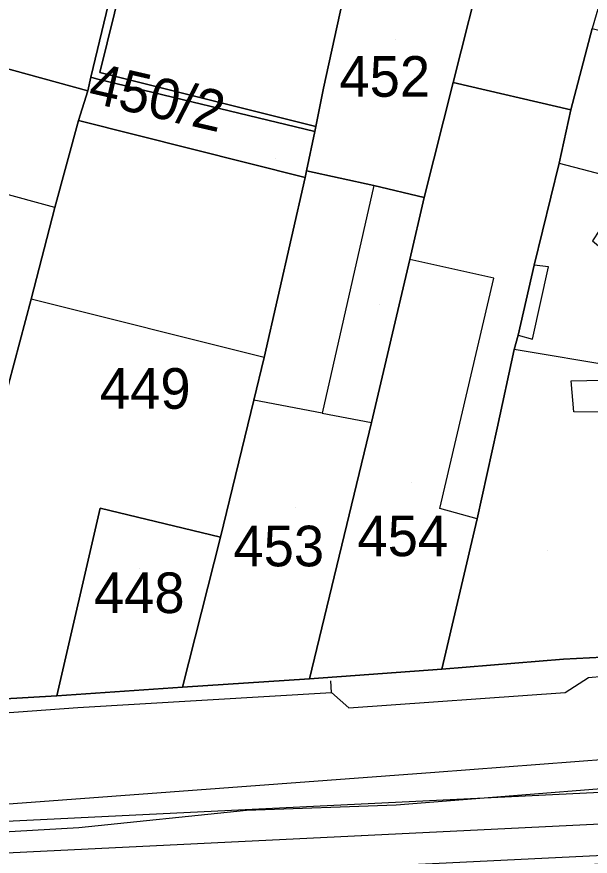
# Model space of a CAD drawing. Extents: x -263423 to -261326, y -1240067 to -1237864.
# Drawn here: x -262993.57 to -262965.35, y -1239820.47 to -1239779.18 of the extents above; entities that cross this region are included whole.
import ezdxf

# ---------------------------------------------------------------- set-up
doc = ezdxf.new("R2010")
doc.units = 0
for name, color, linetype in [('body_kn', 7, 'Continuous'), ('kladpar_druhypozemkov', 7, 'Continuous'), ('kladpar_hranice', 7, 'Continuous'), ('kladpar_parcelnecisla', 7, 'Continuous'), ('kladpar_plochy', 7, 'Continuous'), ('tarchy_linie', 7, 'Continuous'), ('zappar_hrandruhpozemk', 7, 'Continuous')]:
    doc.layers.add(name, color=color, linetype=linetype)

msp = doc.modelspace()

# ---------------------------------------------------------------- linework, layer by layer
at = {"layer": 'body_kn'}
for p, q in [((-262989.49, -1239781.92), (-262989.49, -1239781.92)), ((-262989.92, -1239782.15), (-262989.92, -1239782.15)), ((-262989.92, -1239782.15), (-262989.92, -1239782.15)), ((-262989.64, -1239782.22), (-262989.64, -1239782.22)), ((-262972.09, -1239782.4), (-262972.09, -1239782.4)), ((-262990.08, -1239782.82), (-262990.08, -1239782.82)), ((-262990.08, -1239782.82), (-262990.08, -1239782.82)), ((-262978.47, -1239782.68), (-262978.47, -1239782.68)), ((-262966.3, -1239783.76), (-262966.3, -1239783.76)), ((-262990.53, -1239784.28), (-262990.53, -1239784.28)), ((-262978.91, -1239784.81), (-262978.91, -1239784.81)), ((-262978.86, -1239784.57), (-262978.86, -1239784.57)), ((-262978.86, -1239784.57), (-262978.86, -1239784.57)), ((-262966.88, -1239786.37), (-262966.88, -1239786.37)), ((-262966.88, -1239786.37), (-262966.88, -1239786.37)), ((-262979.32, -1239786.76), (-262979.32, -1239786.76)), ((-262979.38, -1239787.08), (-262979.38, -1239787.08)), ((-262979.38, -1239787.08), (-262979.38, -1239787.08)), ((-262976, -1239787.48), (-262976, -1239787.48)), ((-262976, -1239787.48), (-262976, -1239787.48)), ((-262973.52, -1239788.06), (-262973.52, -1239788.06)), ((-262991.7, -1239788.55), (-262991.7, -1239788.55)), ((-262991.7, -1239788.55), (-262991.7, -1239788.55)), ((-262974.23, -1239791.12), (-262974.23, -1239791.12)), ((-262974.23, -1239791.12), (-262974.23, -1239791.12)), ((-262968.11, -1239791.4), (-262968.11, -1239791.4)), ((-262967.41, -1239791.47), (-262967.41, -1239791.47)), ((-262970.09, -1239792.03), (-262970.09, -1239792.03)), ((-262992.86, -1239793.06), (-262992.86, -1239793.06)), ((-262968.89, -1239794.84), (-262968.89, -1239794.84)), ((-262968.89, -1239794.84), (-262968.89, -1239794.84)), ((-262968.19, -1239795.03), (-262968.19, -1239795.03)), ((-262969.09, -1239795.54), (-262969.09, -1239795.54)), ((-262981.4, -1239795.93), (-262981.4, -1239795.93)), ((-262981.4, -1239795.93), (-262981.4, -1239795.93)), ((-262966.29, -1239797.08), (-262966.29, -1239797.08)), ((-262981.91, -1239798.03), (-262981.91, -1239798.03)), ((-262978.54, -1239798.68), (-262978.54, -1239798.68)), ((-262966.16, -1239798.61), (-262966.16, -1239798.61)), ((-262976.12, -1239799.14), (-262976.12, -1239799.14)), ((-262969.93, -1239799.42), (-262969.93, -1239799.42)), ((-262989.46, -1239803.34), (-262989.46, -1239803.34)), ((-262972.75, -1239803.36), (-262972.75, -1239803.36)), ((-262970.91, -1239803.88), (-262970.91, -1239803.88)), ((-262970.91, -1239803.88), (-262970.91, -1239803.88)), ((-262983.54, -1239804.77), (-262983.54, -1239804.77)), ((-262983.54, -1239804.77), (-262983.54, -1239804.77)), ((-262966.66, -1239810.78), (-262966.66, -1239810.78)), ((-262972.66, -1239811.27), (-262972.66, -1239811.27)), ((-262979.16, -1239811.74), (-262979.16, -1239811.74)), ((-262965.44, -1239811.68), (-262965.44, -1239811.68)), ((-262985.42, -1239812.16), (-262985.42, -1239812.16)), ((-262978.11, -1239811.85), (-262978.11, -1239811.85)), ((-262991.6, -1239812.58), (-262991.6, -1239812.58)), ((-262978.09, -1239812.41), (-262978.09, -1239812.41)), ((-262978.09, -1239812.41), (-262978.09, -1239812.41)), ((-262966.58, -1239812.41), (-262966.58, -1239812.41)), ((-262990.57, -1239813.15), (-262990.57, -1239813.15)), ((-262977.23, -1239813.17), (-262977.23, -1239813.17)), ((-262973, -1239816.36), (-262973, -1239816.36)), ((-262974.9, -1239817.94), (-262974.9, -1239817.94)), ((-262982.27, -1239818.21), (-262982.27, -1239818.21)), ((-262990.52, -1239819.05), (-262990.52, -1239819.05))]:
    msp.add_line(p, q, dxfattribs=at)
at = {"layer": 'kladpar_druhypozemkov'}
for p, q in [((-262974.95, -1239780.31), (-262974.95, -1239780.31)), ((-262980.85, -1239786.14), (-262980.85, -1239786.14)), ((-262975.73, -1239793.32), (-262975.73, -1239793.32)), ((-262987.4, -1239797.24), (-262987.4, -1239797.24)), ((-262974.15, -1239802.11), (-262974.15, -1239802.11)), ((-262979.85, -1239803.31), (-262979.85, -1239803.31)), ((-262967.43, -1239805.42), (-262967.43, -1239805.42)), ((-262987.55, -1239806.31), (-262987.55, -1239806.31))]:
    msp.add_line(p, q, dxfattribs=at)
at = {"layer": 'kladpar_hranice'}
for points in [[(-262966.65, -1239760.75), (-262965.09, -1239754.26), (-262959.11, -1239755.69), (-262960.79, -1239761.74), (-262963.71, -1239774.47), (-262965.26, -1239779.75), (-262966.3, -1239783.76), (-262972.09, -1239782.4), (-262970.54, -1239776.22), (-262967.95, -1239765.91), (-262966.65, -1239760.75)], [(-262986.64, -1239768.57), (-262986.9, -1239769.58), (-262986.92, -1239769.66), (-262989.92, -1239782.15), (-262990.08, -1239782.82), (-262996.71, -1239781), (-262993.93, -1239773.56), (-262993.8, -1239772.86), (-262992.64, -1239768.02), (-262991.98, -1239763.5), (-262991.81, -1239763.66), (-262991.95, -1239764.75), (-262991.23, -1239765.39), (-262990.63, -1239764.79), (-262986.64, -1239768.57)], [(-262978.86, -1239784.57), (-262978.91, -1239784.81), (-262989.64, -1239782.22), (-262989.92, -1239782.15), (-262986.92, -1239769.66), (-262982.94, -1239770.71), (-262981.57, -1239765.49), (-262980.39, -1239765.77), (-262980.6, -1239766.46), (-262980.9, -1239767.72), (-262978.84, -1239768.28), (-262981.01, -1239776.61), (-262983.49, -1239776.01), (-262983.23, -1239774.99), (-262987.48, -1239773.91), (-262988.04, -1239776.06), (-262989.49, -1239781.92), (-262978.86, -1239784.57)], [(-262976.72, -1239774.66), (-262978.47, -1239782.68), (-262978.86, -1239784.57), (-262989.49, -1239781.92), (-262988.04, -1239776.06)], [(-262973.98, -1239775.38), (-262970.54, -1239776.22), (-262972.09, -1239782.4), (-262973.52, -1239788.06), (-262976, -1239787.48), (-262979.32, -1239786.76), (-262978.91, -1239784.81), (-262978.86, -1239784.57), (-262978.47, -1239782.68), (-262976.72, -1239774.66), (-262973.98, -1239775.38)], [(-262954.05, -1239782.61), (-262955.67, -1239789.23), (-262957.36, -1239796.36), (-262960.6, -1239810.5), (-262963.47, -1239810.61), (-262966.66, -1239810.78), (-262972.66, -1239811.27), (-262970.91, -1239803.88), (-262969.93, -1239799.42), (-262969.09, -1239795.54), (-262968.89, -1239794.84), (-262968.11, -1239791.4), (-262966.88, -1239786.37), (-262966.3, -1239783.76), (-262965.26, -1239779.75), (-262954.05, -1239782.61)], [(-262990.08, -1239782.82), (-262990.53, -1239784.28), (-262991.7, -1239788.55), (-262992.86, -1239793.06), (-262993.97, -1239797.27), (-262997.54, -1239812.93), (-263005, -1239813.47), (-262999.69, -1239792.78), (-262998.71, -1239788.64), (-262998.26, -1239786.79), (-262996.71, -1239781), (-262990.08, -1239782.82)], [(-262989.92, -1239782.15), (-262989.64, -1239782.22), (-262978.91, -1239784.81), (-262979.32, -1239786.76), (-262979.38, -1239787.08), (-262990.53, -1239784.28), (-262990.08, -1239782.82), (-262989.92, -1239782.15)], [(-262974.23, -1239791.12), (-262973.52, -1239788.06), (-262972.09, -1239782.4), (-262966.3, -1239783.76), (-262966.88, -1239786.37), (-262968.11, -1239791.4), (-262968.89, -1239794.84), (-262969.09, -1239795.54), (-262969.93, -1239799.42), (-262970.91, -1239803.88), (-262972.66, -1239811.27), (-262979.16, -1239811.74), (-262976.12, -1239799.14), (-262974.23, -1239791.12)], [(-262979.38, -1239787.08), (-262981.4, -1239795.93), (-262981.91, -1239798.03), (-262983.54, -1239804.77), (-262989.46, -1239803.34), (-262991.6, -1239812.58), (-262997.54, -1239812.93), (-262993.97, -1239797.27), (-262992.86, -1239793.06), (-262991.7, -1239788.55), (-262990.53, -1239784.28), (-262979.38, -1239787.08)], [(-262976, -1239787.48), (-262973.52, -1239788.06), (-262974.23, -1239791.12), (-262976.12, -1239799.14), (-262979.16, -1239811.74), (-262985.42, -1239812.16), (-262983.54, -1239804.77), (-262981.91, -1239798.03), (-262981.4, -1239795.93), (-262979.38, -1239787.08), (-262979.32, -1239786.76), (-262976, -1239787.48)], [(-262983.54, -1239804.77), (-262985.42, -1239812.16), (-262991.6, -1239812.58), (-262989.46, -1239803.34), (-262983.54, -1239804.77)], [(-263031.67, -1239830.48), (-263030.92, -1239819.01), (-263030.78, -1239815.57), (-263026.31, -1239815.21), (-263024.66, -1239815.15), (-263005, -1239813.47), (-262997.54, -1239812.93), (-262991.6, -1239812.58), (-262985.42, -1239812.16), (-262979.16, -1239811.74), (-262972.66, -1239811.27), (-262966.66, -1239810.78), (-262963.47, -1239810.61), (-262960.6, -1239810.5), (-262954.1, -1239810.21), (-262947.85, -1239809.79)]]:
    msp.add_lwpolyline(points, dxfattribs=at)
at = {"layer": 'kladpar_plochy'}
for points in [[(-262966.65, -1239760.75), (-262965.09, -1239754.26), (-262959.11, -1239755.69), (-262960.79, -1239761.74), (-262963.71, -1239774.47), (-262965.26, -1239779.75), (-262966.3, -1239783.76), (-262972.09, -1239782.4), (-262970.54, -1239776.22), (-262967.95, -1239765.91)], [(-262986.64, -1239768.57), (-262986.9, -1239769.58), (-262986.92, -1239769.66), (-262989.92, -1239782.15), (-262990.08, -1239782.82), (-262996.71, -1239781), (-262993.93, -1239773.56), (-262993.8, -1239772.86), (-262992.64, -1239768.02), (-262991.98, -1239763.5), (-262991.81, -1239763.66), (-262991.95, -1239764.75), (-262991.23, -1239765.39), (-262990.63, -1239764.79)], [(-262978.86, -1239784.57), (-262978.91, -1239784.81), (-262989.64, -1239782.22), (-262989.92, -1239782.15), (-262986.92, -1239769.66), (-262982.94, -1239770.71), (-262981.57, -1239765.49), (-262980.39, -1239765.77), (-262980.6, -1239766.46), (-262980.9, -1239767.72), (-262978.84, -1239768.28), (-262981.01, -1239776.61), (-262983.49, -1239776.01), (-262983.23, -1239774.99), (-262987.48, -1239773.91), (-262988.04, -1239776.06), (-262989.49, -1239781.92)], [(-262973.98, -1239775.38), (-262970.54, -1239776.22), (-262972.09, -1239782.4), (-262973.52, -1239788.06), (-262976, -1239787.48), (-262979.32, -1239786.76), (-262978.91, -1239784.81), (-262978.86, -1239784.57), (-262978.47, -1239782.68), (-262976.72, -1239774.66)], [(-262954.05, -1239782.61), (-262955.67, -1239789.23), (-262957.36, -1239796.36), (-262960.6, -1239810.5), (-262963.47, -1239810.61), (-262966.66, -1239810.78), (-262972.66, -1239811.27), (-262970.91, -1239803.88), (-262969.93, -1239799.42), (-262969.09, -1239795.54), (-262968.89, -1239794.84), (-262968.11, -1239791.4), (-262966.88, -1239786.37), (-262966.3, -1239783.76), (-262965.26, -1239779.75)], [(-262990.08, -1239782.82), (-262990.53, -1239784.28), (-262991.7, -1239788.55), (-262992.86, -1239793.06), (-262993.97, -1239797.27), (-262997.54, -1239812.93), (-263005, -1239813.47), (-262999.69, -1239792.78), (-262998.71, -1239788.64), (-262998.26, -1239786.79), (-262996.71, -1239781)], [(-262989.92, -1239782.15), (-262989.64, -1239782.22), (-262978.91, -1239784.81), (-262979.32, -1239786.76), (-262979.38, -1239787.08), (-262990.53, -1239784.28), (-262990.08, -1239782.82)], [(-262974.23, -1239791.12), (-262973.52, -1239788.06), (-262972.09, -1239782.4), (-262966.3, -1239783.76), (-262966.88, -1239786.37), (-262968.11, -1239791.4), (-262968.89, -1239794.84), (-262969.09, -1239795.54), (-262969.93, -1239799.42), (-262970.91, -1239803.88), (-262972.66, -1239811.27), (-262979.16, -1239811.74), (-262976.12, -1239799.14)], [(-262979.38, -1239787.08), (-262981.4, -1239795.93), (-262981.91, -1239798.03), (-262983.54, -1239804.77), (-262989.46, -1239803.34), (-262991.6, -1239812.58), (-262997.54, -1239812.93), (-262993.97, -1239797.27), (-262992.86, -1239793.06), (-262991.7, -1239788.55), (-262990.53, -1239784.28)], [(-262976, -1239787.48), (-262973.52, -1239788.06), (-262974.23, -1239791.12), (-262976.12, -1239799.14), (-262979.16, -1239811.74), (-262985.42, -1239812.16), (-262983.54, -1239804.77), (-262981.91, -1239798.03), (-262981.4, -1239795.93), (-262979.38, -1239787.08), (-262979.32, -1239786.76)], [(-262983.54, -1239804.77), (-262985.42, -1239812.16), (-262991.6, -1239812.58), (-262989.46, -1239803.34)]]:
    msp.add_lwpolyline(points, close=True, dxfattribs=at)
for points in [[(-262976.72, -1239774.66), (-262978.47, -1239782.68), (-262978.86, -1239784.57), (-262989.49, -1239781.92), (-262988.04, -1239776.06)], [(-263031.67, -1239830.48), (-263030.92, -1239819.01), (-263030.78, -1239815.57), (-263026.31, -1239815.21), (-263024.66, -1239815.15), (-263005, -1239813.47), (-262997.54, -1239812.93), (-262991.6, -1239812.58), (-262985.42, -1239812.16), (-262979.16, -1239811.74), (-262972.66, -1239811.27), (-262966.66, -1239810.78), (-262963.47, -1239810.61), (-262960.6, -1239810.5), (-262954.1, -1239810.21), (-262947.85, -1239809.79), (-262945.55, -1239809.61), (-262941.85, -1239809.44), (-262937.9, -1239809.08), (-262935.03, -1239808.9), (-262929.16, -1239808.4), (-262927.24, -1239808.23)]]:
    msp.add_lwpolyline(points, dxfattribs=at)
at = {"layer": 'tarchy_linie'}
msp.add_line((-262978.09, -1239812.41), (-262978.11, -1239811.85), dxfattribs=at)
for points in [[(-263038.73, -1239806.72), (-263031.38, -1239816.09), (-263026.39, -1239815.83), (-263023.48, -1239815.66), (-263016.25, -1239815.45), (-263007.28, -1239815.08), (-263001.93, -1239813.95), (-262999.8, -1239813.82), (-262990.57, -1239813.15), (-262978.09, -1239812.41), (-262977.23, -1239813.17), (-262966.58, -1239812.41), (-262965.44, -1239811.68), (-262964.69, -1239811.62), (-262963.25, -1239812.34), (-262962.69, -1239812.33), (-262954.08, -1239811.71), (-262947.55, -1239811.24), (-262941.7, -1239810.91), (-262936.84, -1239810.59), (-262926.96, -1239809.83)], [(-263040.71, -1239822.61), (-263028.21, -1239821.58), (-263011.41, -1239820.35), (-263009.68, -1239820.43), (-263005.6, -1239819.97), (-262996.8, -1239819.42), (-262990.52, -1239819.05), (-262982.27, -1239818.21), (-262974.9, -1239817.94), (-262961.71, -1239816.9), (-262957.13, -1239816.67), (-262951.22, -1239816.14), (-262935.08, -1239814.96), (-262920.83, -1239813.88), (-262915.8, -1239814.33), (-262912.45, -1239815.09), (-262910.37, -1239815.48), (-262904.67, -1239816.87), (-262900.33, -1239817.77), (-262879.71, -1239823.02)], [(-263037.12, -1239820.85), (-262910.42, -1239814.67), (-262904.24, -1239815.14), (-262880.51, -1239820.63), (-262880.88, -1239822.14), (-262880.99, -1239822.6), (-262877.97, -1239823.34), (-262877.85, -1239822.84), (-262877.48, -1239821.33), (-262844.24, -1239829.02), (-262814.48, -1239915.4), (-262784.13, -1239904.88), (-262744.13, -1239891.33), (-262716.19, -1239882.12)], [(-263042.81, -1239822.68), (-262910.44, -1239816.22), (-262904.59, -1239816.65)], [(-263035.06, -1239823.85), (-262911.88, -1239817.84), (-262911.79, -1239819.21), (-262913.26, -1239818.86), (-262953.73, -1239820.06), (-262994.41, -1239822.97), (-263033.31, -1239826.41), (-263035.06, -1239823.85)]]:
    msp.add_lwpolyline(points, dxfattribs=at)
at = {"layer": 'zappar_hrandruhpozemk'}
for p, q in [((-262991.7, -1239788.55), (-262998.26, -1239786.79)), ((-262976, -1239787.48), (-262978.54, -1239798.68)), ((-262970.09, -1239792.03), (-262974.23, -1239791.12)), ((-262968.19, -1239795.03), (-262967.41, -1239791.47)), ((-262967.41, -1239791.47), (-262968.11, -1239791.4)), ((-262981.4, -1239795.93), (-262992.86, -1239793.06)), ((-262968.89, -1239794.84), (-262968.19, -1239795.03)), ((-262978.54, -1239798.68), (-262981.91, -1239798.03)), ((-262978.54, -1239798.68), (-262976.12, -1239799.14)), ((-262919.74, -1239812.29), (-262973, -1239816.36))]:
    msp.add_line(p, q, dxfattribs=at)
for points in [[(-262966.88, -1239786.37), (-262962.93, -1239787.41), (-262963.12, -1239788.05), (-262964.21, -1239788.62), (-262965.24, -1239790.2), (-262963.59, -1239791.55)], [(-262970.91, -1239803.88), (-262972.75, -1239803.36), (-262970.09, -1239792.03)], [(-262962.23, -1239802.78), (-262963.31, -1239802.13), (-262962.66, -1239799.14), (-262963.62, -1239799.33), (-262964.89, -1239798.62), (-262966.16, -1239798.61), (-262966.29, -1239797.08), (-262963.99, -1239797.03), (-262963.99, -1239796.39), (-262969.09, -1239795.54)], [(-262973, -1239816.36), (-263027.99, -1239820.43), (-263029.4, -1239820.1), (-263030.92, -1239819.01)]]:
    msp.add_lwpolyline(points, dxfattribs=at)

# ---------------------------------------------------------------- texts
at = {"layer": 'kladpar_parcelnecisla'}
for s, p in [('452', (-262977.691, -1239783.11)), ('449', (-262989.479, -1239798.46)), ('454', (-262976.804, -1239805.71)), ('453', (-262982.907, -1239806.21)), ('448', (-262989.773, -1239808.51))]:
    msp.add_text(s, height=2, dxfattribs=at).set_placement(p)
msp.add_text('450/2', height=2, rotation=347, dxfattribs=at).set_placement((-262990.129, -1239783.357))

doc.saveas('drawing.dxf')
